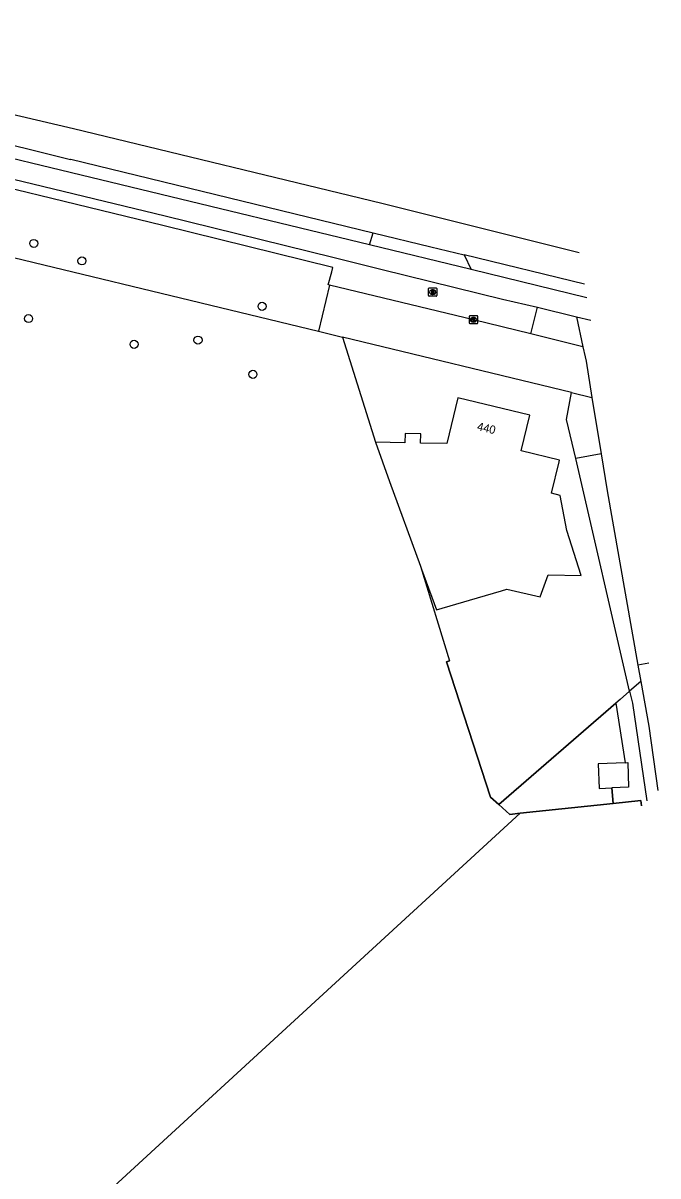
# Model space of a CAD drawing. Extents: x 163268 to 164360, y 381529 to 382285.
# Drawn here: x 164283.2 to 164360.4, y 382042.2 to 382182.4 of the extents above; entities that cross this region are included whole.
import ezdxf

# ---------------------------------------------------------------- set-up
doc = ezdxf.new("R2010")
doc.units = 0
for name, color, linetype in [('IMGEO_Berm_groen', 7, 'Continuous'), ('IMGEO_Boom', 7, 'Continuous'), ('IMGEO_Fietspad_gesloten', 7, 'Continuous'), ('IMGEO_Fietspad_open', 7, 'Continuous'), ('IMGEO_Gemengd_bos', 7, 'Continuous'), ('IMGEO_Groenvoorziening', 7, 'Continuous'), ('IMGEO_Hek', 7, 'Continuous'), ('IMGEO_Kolk', 7, 'Continuous'), ('IMGEO_Loofbos', 7, 'Continuous'), ('IMGEO_Muur', 7, 'Continuous'), ('IMGEO_Pand', 7, 'Continuous'), ('IMGEO_Pand_nummerreeks', 7, 'Continuous'), ('IMGEO_Parkeervlak_open', 7, 'Continuous'), ('IMGEO_Rijbaan_lokaal_halfverhard', 7, 'Continuous'), ('IMGEO_Rijbaan_lokaal_open', 7, 'Continuous'), ('IMGEO_Rijbaan_regionaal_gesloten', 7, 'Continuous'), ('IMGEO_Rioolput', 7, 'Continuous'), ('IMGEO_Verkeerseiland_groen', 7, 'Continuous'), ('IMGEO_Voetpad_open', 7, 'Continuous')]:
    doc.layers.add(name, color=color, linetype=linetype)

msp = doc.modelspace()

# ---------------------------------------------------------------- linework, layer by layer
at = {"layer": 'IMGEO_Berm_groen'}
msp.add_lwpolyline([(164221.08, 382168.63), (164319.15, 382144.94)], dxfattribs=at)
at = {"layer": 'IMGEO_Boom'}
for centre in [(164284.53, 382155.62), (164290.39, 382153.5), (164312.29, 382147.97), (164283.89, 382146.48), (164296.73, 382143.35), (164304.5, 382143.86), (164311.18, 382139.7)]:
    msp.add_circle(centre, 0.489, dxfattribs=at)
at = {"layer": 'IMGEO_Fietspad_gesloten'}
for points in [[(164325.37, 382155.44), (164269.61, 382168.91)], [(164270.8, 382166.13), (164300.51, 382158.96), (164320.88, 382153.95), (164326.91, 382152.44), (164341.52, 382148.86), (164345.77, 382147.86)], [(164337.72, 382152.46), (164325.37, 382155.44)], [(164351.79, 382149.02), (164337.72, 382152.46)], [(164345.77, 382147.86), (164350.55, 382146.69)]]:
    msp.add_lwpolyline(points, dxfattribs=at)
at = {"layer": 'IMGEO_Fietspad_open'}
msp.add_lwpolyline([(164336.87, 382154.23), (164337.72, 382152.46)], dxfattribs=at)
at = {"layer": 'IMGEO_Gemengd_bos'}
for points in [[(164322.09, 382144.23), (164326.07, 382131.44)], [(164331.56, 382116.36), (164335.09, 382104.86), (164334.72, 382104.74), (164340.08, 382088.27), (164341.07, 382087.39)], [(164343.68, 382086.33), (164245.87, 381996.51)]]:
    msp.add_lwpolyline(points, dxfattribs=at)
at = {"layer": 'IMGEO_Groenvoorziening'}
msp.add_lwpolyline([(164350.43, 382129.46), (164349.33, 382134.2), (164349.91, 382137.51)], dxfattribs=at)
at = {"layer": 'IMGEO_Hek'}
for points in [[(164341.07, 382087.39), (164340.08, 382088.27), (164334.72, 382104.74), (164335.09, 382104.86)], [(164355.3, 382099.7), (164356.43, 382092.46)], [(164354.98, 382087.51), (164354.83, 382089.41)], [(164354.98, 382087.51), (164358.35, 382087.86)], [(164358.35, 382087.86), (164358.42, 382087.21)], [(164245.87, 381996.51), (164343.68, 382086.33)], [(164343.68, 382086.33), (164342.44, 382086.17), (164341.07, 382087.39)], [(164343.68, 382086.33), (164354.98, 382087.51)]]:
    msp.add_lwpolyline(points, dxfattribs=at)
at = {"layer": 'IMGEO_Kolk'}
for p, q in [((164337.5, 382145.92), (164337.5, 382146.77)), ((164337.58, 382146.85), (164338.43, 382146.85)), ((164337.99, 382146.62), (164338.02, 382146.62)), ((164338.5, 382146.77), (164338.5, 382145.92)), ((164338.43, 382145.84), (164337.58, 382145.84)), ((164338.01, 382146.07), (164337.99, 382146.07))]:
    msp.add_line(p, q, dxfattribs=at)
for points in [[(164337.5, 382145.92), (164337.5, 382146.77)], [(164337.58, 382146.85), (164338.43, 382146.85)], [(164338.5, 382146.77), (164338.5, 382145.92)], [(164338.43, 382145.84), (164337.58, 382145.84)], [(164337.82, 382146.54), (164337.95, 382146.54), (164337.95, 382146.39), (164338.08, 382146.54), (164338.24, 382146.54), (164338.1, 382146.39), (164338.25, 382146.14), (164338.1, 382146.14), (164338.01, 382146.31), (164337.95, 382146.24), (164337.95, 382146.14), (164337.82, 382146.14), (164337.82, 382146.54)]]:
    msp.add_lwpolyline(points, dxfattribs=at)
for centre, start, end in [((164337.58, 382146.77), 91.552, 178.448), ((164337.58, 382146.77), 91.552, 178.448), ((164338.43, 382146.77), 1.552, 88.448), ((164338.43, 382146.77), 1.552, 88.448), ((164337.58, 382145.92), 181.552, 268.448), ((164337.58, 382145.92), 181.552, 268.448), ((164338.43, 382145.92), 271.552, 358.448), ((164338.43, 382145.92), 271.552, 358.448)]:
    msp.add_arc(centre, 0.0765, start, end, dxfattribs=at)
for centre, major_axis, ratio, start_param, end_param in [((164337.99, 382146.34), (-0.387, 0.002), 0.722429, 4.712389, 7.853982), ((164338.01, 382146.34), (-0.39, 0.002), 0.717154, 1.570796, 4.712389)]:
    msp.add_ellipse(centre, major_axis=major_axis, ratio=ratio, start_param=start_param, end_param=end_param, dxfattribs=at)
at = {"layer": 'IMGEO_Loofbos'}
for points in [[(164356.98, 382101.16), (164355.82, 382100.15), (164355.3, 382099.7)], [(164356.98, 382101.16), (164357.32, 382099.73), (164359.08, 382087.82)], [(164341.07, 382087.39), (164355.3, 382099.7)], [(164355.3, 382099.7), (164356.43, 382092.46)], [(164354.83, 382089.41), (164354.98, 382087.51)], [(164358.42, 382087.21), (164358.35, 382087.86), (164354.98, 382087.51)], [(164341.07, 382087.39), (164342.44, 382086.17), (164343.68, 382086.33)], [(164354.98, 382087.51), (164343.68, 382086.33)]]:
    msp.add_lwpolyline(points, dxfattribs=at)
at = {"layer": 'IMGEO_Muur'}
for points in [[(164355.3, 382099.7), (164341.07, 382087.39)], [(164355.82, 382100.15), (164355.3, 382099.7)]]:
    msp.add_lwpolyline(points, dxfattribs=at)
at = {"layer": 'IMGEO_Pand'}
for points in [[(164331.56, 382116.36), (164331.7, 382116), (164333.51, 382111.07), (164337.51, 382112.24), (164341.41, 382113.38), (164342.05, 382113.57), (164346.11, 382112.63), (164347.08, 382115.3), (164351.08, 382115.23), (164349.36, 382120.69), (164348.55, 382124.98), (164347.5, 382125.23), (164348.42, 382129.08), (164348.46, 382129.27), (164343.81, 382130.38), (164344.86, 382134.75), (164336.11, 382136.85), (164334.77, 382131.28), (164331.57, 382131.34), (164331.59, 382132.46), (164329.69, 382132.49), (164329.67, 382131.37), (164326.07, 382131.44)], [(164326.07, 382131.44), (164327.78, 382126.68), (164331.56, 382116.36)], [(164356.43, 382092.46), (164353.17, 382092.34), (164353.29, 382089.35), (164354.83, 382089.41)], [(164356.43, 382092.46), (164356.76, 382092.48), (164356.87, 382089.49), (164354.83, 382089.41)]]:
    msp.add_lwpolyline(points, dxfattribs=at)
at = {"layer": 'IMGEO_Parkeervlak_open'}
for points in [[(164320.49, 382150.55), (164319.15, 382144.94)], [(164319.15, 382144.94), (164322.09, 382144.23)], [(164349.91, 382137.51), (164322.09, 382144.23)], [(164349.91, 382137.51), (164352.4, 382136.89)]]:
    msp.add_lwpolyline(points, dxfattribs=at)
at = {"layer": 'IMGEO_Rijbaan_lokaal_halfverhard'}
for points in [[(164358, 382104.32), (164358.35, 382102.34)], [(164358.35, 382102.34), (164359.32, 382096.91), (164360.43, 382089.08)]]:
    msp.add_lwpolyline(points, dxfattribs=at)
at = {"layer": 'IMGEO_Rijbaan_lokaal_open'}
for points in [[(164350.55, 382146.69), (164351.32, 382143.06)], [(164350.55, 382146.69), (164352.26, 382146.27)], [(164351.32, 382143.06), (164351.58, 382141.82), (164351.69, 382141.32), (164352.4, 382136.89)], [(164352.4, 382136.89), (164353.51, 382130.05)], [(164353.51, 382130.05), (164354.24, 382125.53), (164358, 382104.32)], [(164359.32, 382104.56), (164358, 382104.32)]]:
    msp.add_lwpolyline(points, dxfattribs=at)
at = {"layer": 'IMGEO_Rijbaan_regionaal_gesloten'}
for points in [[(164233.51, 382182.42), (164251.69, 382178.66), (164276.52, 382172.6), (164289.37, 382169.6), (164326.85, 382160.5), (164350.86, 382154.51)], [(164256.64, 382173.61), (164260.59, 382172.88), (164264.36, 382171.93), (164264.36, 382171.89), (164277.06, 382168.8), (164288.98, 382165.83), (164289.02, 382165.88), (164325.8, 382156.92)], [(164325.8, 382156.92), (164332.82, 382155.21), (164336.87, 382154.23)], [(164351.52, 382150.65), (164336.87, 382154.23)]]:
    msp.add_lwpolyline(points, dxfattribs=at)
at = {"layer": 'IMGEO_Rioolput'}
for p, q in [((164332.54, 382149.27), (164332.54, 382150.12)), ((164332.61, 382150.2), (164333.47, 382150.2)), ((164333.05, 382149.42), (164333.02, 382149.42)), ((164333.03, 382149.98), (164333.05, 382149.98)), ((164333.54, 382150.12), (164333.54, 382149.27)), ((164333.47, 382149.2), (164332.61, 382149.2))]:
    msp.add_line(p, q, dxfattribs=at)
for points in [[(164332.54, 382149.27), (164332.54, 382150.12)], [(164332.61, 382150.2), (164333.47, 382150.2)], [(164333.13, 382149.89), (164332.88, 382149.9), (164332.88, 382149.5)], [(164332.88, 382149.5), (164333, 382149.5), (164333, 382149.66), (164333.01, 382149.66)], [(164333.05, 382149.82), (164333, 382149.82), (164333, 382149.73)], [(164333, 382149.73), (164333.05, 382149.73)], [(164333.06, 382149.63), (164333.13, 382149.5), (164333.27, 382149.5), (164333.2, 382149.62)], [(164333.54, 382150.12), (164333.54, 382149.27)], [(164333.47, 382149.2), (164332.61, 382149.2)]]:
    msp.add_lwpolyline(points, dxfattribs=at)
for centre, radius, start, end in [((164332.62, 382150.12), 0.0765, 91.552, 178.448), ((164332.62, 382150.12), 0.0765, 91.552, 178.448), ((164333.01, 382149.61), 0.0533, 26.0293, 88.6989), ((164333.06, 382149.72), 0.0964, 77.0061, 93.1865), ((164333.04, 382149.92), 0.19, 274.7715, 282.9687), ((164333.07, 382149.78), 0.0378, 276.6634, 79.6772), ((164333.13, 382149.79), 0.109, 350.3612, 89.416), ((164333.13, 382149.78), 0.112, 277.5842, 350.9817), ((164333.11, 382149.57), 0.108, 29.5134, 73.7905), ((164333.46, 382150.12), 0.0765, 1.552, 88.448), ((164333.46, 382150.12), 0.0765, 1.552, 88.448), ((164332.62, 382149.27), 0.0765, 181.552, 268.448), ((164332.62, 382149.27), 0.0765, 181.552, 268.448), ((164333.46, 382149.27), 0.0765, 271.552, 358.448), ((164333.46, 382149.27), 0.0765, 271.552, 358.448)]:
    msp.add_arc(centre, radius, start, end, dxfattribs=at)
for centre, major_axis, ratio, start_param, end_param in [((164333.03, 382149.7), (-0.387, 0.002), 0.722429, 4.712389, 7.853982), ((164333.05, 382149.7), (-0.39, 0.002), 0.717154, 1.570796, 4.712389)]:
    msp.add_ellipse(centre, major_axis=major_axis, ratio=ratio, start_param=start_param, end_param=end_param, dxfattribs=at)
at = {"layer": 'IMGEO_Verkeerseiland_groen'}
msp.add_lwpolyline([(164325.37, 382155.44), (164325.8, 382156.92)], dxfattribs=at)
at = {"layer": 'IMGEO_Voetpad_open'}
for points in [[(164320.49, 382150.55), (164320.35, 382150.58), (164320.76, 382152.18), (164320.88, 382152.7), (164300.24, 382157.8), (164268.86, 382165.41)], [(164344.98, 382144.62), (164338, 382146.34), (164320.49, 382150.55)], [(164344.98, 382144.62), (164345.77, 382147.86)], [(164351.32, 382143.06), (164344.98, 382144.62)], [(164353.51, 382130.05), (164350.43, 382129.46)], [(164356.98, 382101.16), (164350.43, 382129.46)], [(164358.35, 382102.34), (164356.98, 382101.16)]]:
    msp.add_lwpolyline(points, dxfattribs=at)

# ---------------------------------------------------------------- texts
at = {"layer": 'IMGEO_Pand_nummerreeks'}
msp.add_text('440', height=1, rotation=346.5355, dxfattribs=at).set_placement((164338.38, 382132.93))

doc.saveas('drawing.dxf')
